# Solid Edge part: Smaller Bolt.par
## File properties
Author: m_hel
Template: iso metric part.par
Last saved by: m_hel
Revision: 4
Application: Solid Edge
Accuracy: 0,990
Username: m_hel
Material: Rubber
Face Style: Black (dull)
Fill Style: Normal
Virtual Style: Normal
Grouping: Uncategorized
LibraryName: Custom Materials
Coef. of Thermal Exp: 0.0
Thermal Conductivity: 0.0
Specific Heat: 0.0
Modulus of Elasticity: 0.0
Poisson's Ratio: 0.0
Yield Stress: 0.0
Ultimate Stress: 0.0
Elongation: 0.0
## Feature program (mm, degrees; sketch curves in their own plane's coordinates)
sketch for "unnamed Protrusion 1" plane through (0, 0, 0) normal (1, 0, 0) x-axis (0, 1, 0)
  circle centre (0, 0) radius 10
extrude "unnamed Protrusion 1" add finite 90 symmetric
sketch for "ExtrudedProtrusion_2" plane through (45, 0, 0) normal (1, 0, 0) x-axis (0, 1, 0)
  circle centre (0, 0) radius 20
extrude "ExtrudedProtrusion_2" add finite 5 along +normal
sketch for "ExtrudedProtrusion_3" plane through (50, 0, 0) normal (1, 0, 0) x-axis (0, 1, 0)
  line (15, 8.6603) -> (0, 17.3205)
  line (0, 17.3205) -> (-15, 8.6603)
  line (-15, 8.6603) -> (-15, -8.6603)
  line (-15, -8.6603) -> (0, -17.3205)
  line (0, -17.3205) -> (15, -8.6603)
  line (15, -8.6603) -> (15, 8.6603)
extrude "ExtrudedProtrusion_3" add finite 20 along +normal
chamfer "Chamfer_1" setback 3
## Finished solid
Body 1: solid body, 13 faces, 23 edges, 12 vertices.
  Faces by surface: plane 10, cylinder 2, cone 1
  Edges by curve: line 18, circle 5
Bounding box of the edges (mm): 115.000 x 40.000 x 40.000, from (-45, -20, -20) to (70, 20, 20).
Cylindrical faces by radius (mm): R10 x1, R20 x1
Conical faces (half-angle, radius in mm at the cone's reference point): 45 deg R7 x1
Planar faces by outward normal: +x 2, +y 1, -x 2, -y 1, oblique 4
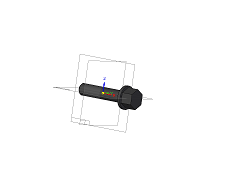
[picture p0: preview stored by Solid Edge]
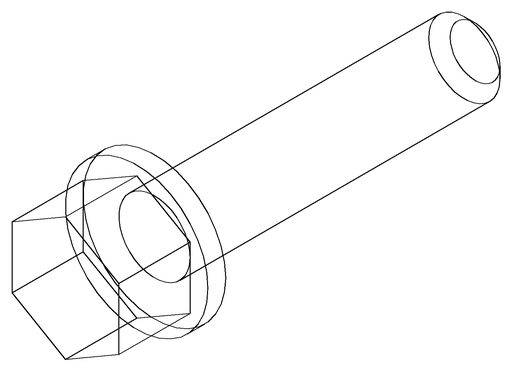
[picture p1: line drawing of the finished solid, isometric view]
